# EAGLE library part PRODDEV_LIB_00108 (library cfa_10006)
CFAG12864E-WGH-TN, 128x64 STN Positive, Gray, Transflective, White EL Backlit LCD Module with EL Inverter on board
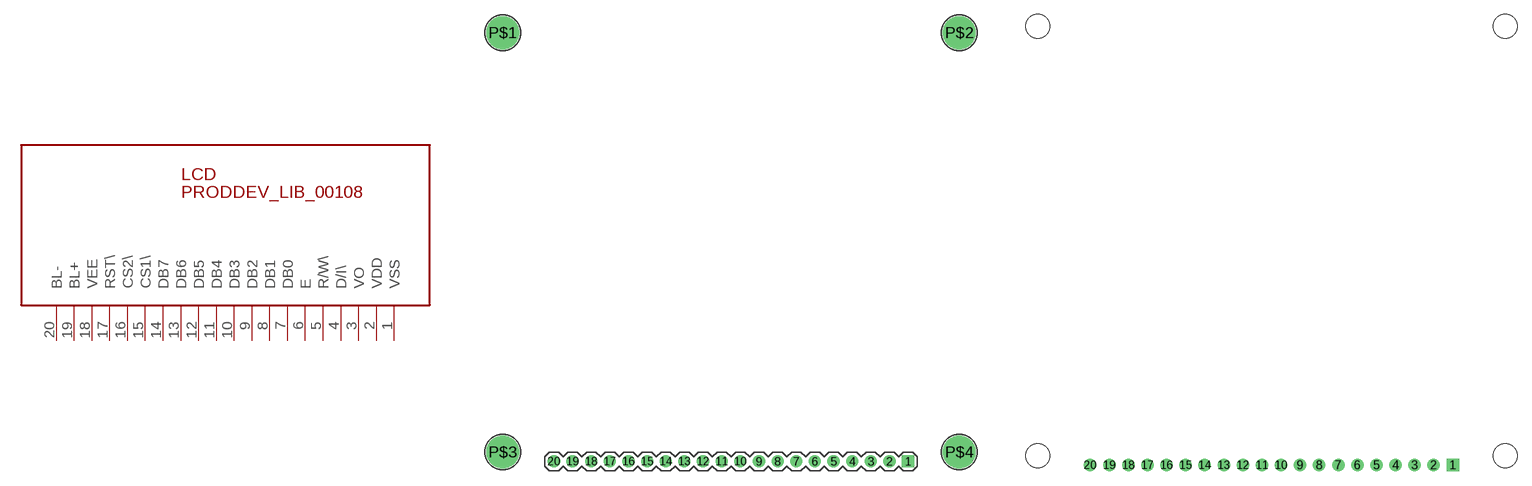
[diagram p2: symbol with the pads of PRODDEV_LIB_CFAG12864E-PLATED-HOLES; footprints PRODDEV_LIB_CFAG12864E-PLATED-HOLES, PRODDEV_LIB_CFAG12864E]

Designator prefix LCD

## PRODDEV_LIB_00108  [PRODDEV_LIB_CFAG12864E-PLATED-HOLES]
1  VSS  pwr
2  VDD  pwr
3  VO  pas
4  D/I\  in
5  R/W\  in
6  E  in
7  DB0
8  DB1
9  DB2
10  DB3
11  DB4
12  DB5
13  DB6
14  DB7
15  CS1\  in
16  CS2\  in
17  RST\  in
18  VEE  pas
19  BL+  pas
20  BL-  pas

## PRODDEV_LIB_00108NON-PLATED-HOLES  [PRODDEV_LIB_CFAG12864E]
Pads as for PRODDEV_LIB_CFAG12864E-PLATED-HOLES

## Footprint PRODDEV_LIB_CFAG12864E-PLATED-HOLES (pad centres in mm)
drill 0.8 square: 1 38,0
drill 0.8 round: 2 36,0; 3 34,0; 4 32,0; 5 30,0; 6 28,0; 7 26,0; 8 24,0; 9 22,0; 10 20,0; 11 18,0; 12 16,0; 13 14,0; 14 12,0; 15 10,0; 16 8,0; 17 6,0; 18 4,0; 19 2,0; 20 0,0
drill 2.5 round: P$1 -5.5,46; P$2 43.5,46; P$3 -5.5,1; P$4 43.5,1

## Footprint PRODDEV_LIB_CFAG12864E (pad centres in mm)
drill 0.8 square: 1 38,0
drill 0.8 round: 2 36,0; 3 34,0; 4 32,0; 5 30,0; 6 28,0; 7 26,0; 8 24,0; 9 22,0; 10 20,0; 11 18,0; 12 16,0; 13 14,0; 14 12,0; 15 10,0; 16 8,0; 17 6,0; 18 4,0; 19 2,0; 20 0,0
hole 2.5 at -5.5,46
hole 2.5 at 43.5,46
hole 2.5 at 43.5,1
hole 2.5 at -5.5,1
